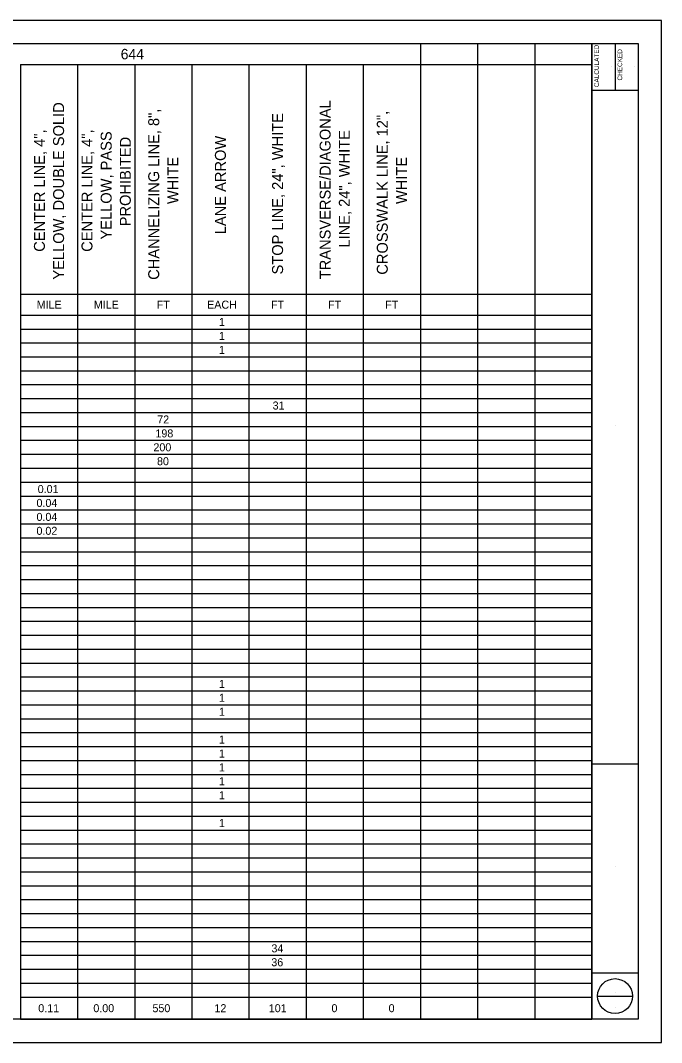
# Model space of a CAD drawing. Extents: x 10.3 to 44.3, y 3.4 to 25.4.
# Drawn here: x 30.51 to 44.31, y 3.4 to 25.4 of the extents above; entities that cross this region are included whole.
import ezdxf

# ---------------------------------------------------------------- set-up
doc = ezdxf.new("R2010")
doc.units = 0
for name, color, linetype in [('SH_Border', 7, 'Continuous'), ('SH_Cut_Line', 7, 'Continuous'), ('SH_Data', 7, 'Continuous'), ('SH_Text', 7, 'Continuous')]:
    doc.layers.add(name, color=color, linetype=linetype)

msp = doc.modelspace()

# ---------------------------------------------------------------- linework, layer by layer
at = {"layer": 'SH_Border'}
for p, q in [((42.806, 3.905), (42.806, 24.905)), ((43.306, 24.905), (43.306, 23.905)), ((42.806, 23.905), (43.806, 23.905)), ((42.806, 9.405), (43.806, 9.405)), ((42.806, 4.905), (43.806, 4.905))]:
    msp.add_line(p, q, dxfattribs=at)
msp.add_lwpolyline([(12.306, 24.905), (43.806, 24.905), (43.806, 3.905), (12.306, 3.905)], close=True, dxfattribs=at)
at = {"layer": 'SH_Cut_Line'}
msp.add_lwpolyline([(10.306, 3.405), (44.306, 3.405), (44.306, 25.405), (10.306, 25.405)], close=True, dxfattribs=at)
at = {"layer": 'SH_Data'}
for p, q in [((43.226, 24.408), (43.226, 24.408)), ((43.726, 24.408), (43.726, 24.408)), ((43.306, 16.696), (43.306, 16.696)), ((43.306, 7.196), (43.306, 7.196)), ((42.931, 4.405), (43.681, 4.405)), ((43.306, 4.49), (43.306, 4.49)), ((43.306, 4.15), (43.306, 4.15))]:
    msp.add_line(p, q, dxfattribs=at)
msp.add_circle((43.306, 4.405), 0.375, dxfattribs=at)
at = {"layer": 'SH_Text'}
for p, q in [((30.512, 24.905), (34.2, 24.905)), ((34.2, 24.905), (36.659, 24.905)), ((36.659, 24.905), (41.577, 24.905)), ((39.118, 24.905), (39.118, 12.173)), ((40.347, 24.905), (40.347, 12.173)), ((41.577, 24.905), (42.806, 24.905)), ((41.577, 24.905), (41.577, 12.173)), ((42.806, 24.905), (42.806, 12.173)), ((30.512, 24.455), (34.2, 24.455)), ((30.512, 24.455), (30.512, 12.173)), ((31.741, 24.455), (31.741, 12.173)), ((32.97, 24.455), (32.97, 12.173)), ((34.2, 24.455), (36.659, 24.455)), ((34.2, 24.455), (34.2, 12.173)), ((35.429, 24.455), (35.429, 12.173)), ((36.659, 24.455), (41.577, 24.455)), ((36.659, 24.455), (36.659, 12.173)), ((37.888, 24.455), (37.888, 12.173)), ((41.577, 24.455), (42.806, 24.455)), ((30.512, 19.512), (34.2, 19.512)), ((34.2, 19.512), (36.659, 19.512)), ((36.659, 19.512), (41.577, 19.512)), ((41.577, 19.512), (42.806, 19.512)), ((30.512, 19.063), (34.2, 19.063)), ((34.2, 19.063), (36.659, 19.063)), ((36.659, 19.063), (41.577, 19.063)), ((41.577, 19.063), (42.806, 19.063)), ((30.512, 18.763), (34.2, 18.763)), ((34.2, 18.763), (36.659, 18.763)), ((36.659, 18.763), (41.577, 18.763)), ((41.577, 18.763), (42.806, 18.763)), ((30.512, 18.464), (34.2, 18.464)), ((34.2, 18.464), (36.659, 18.464)), ((36.659, 18.464), (41.577, 18.464)), ((41.577, 18.464), (42.806, 18.464)), ((30.512, 18.164), (34.2, 18.164)), ((34.2, 18.164), (36.659, 18.164)), ((36.659, 18.164), (41.577, 18.164)), ((41.577, 18.164), (42.806, 18.164)), ((30.512, 17.865), (34.2, 17.865)), ((34.2, 17.865), (36.659, 17.865)), ((36.659, 17.865), (41.577, 17.865)), ((41.577, 17.865), (42.806, 17.865)), ((30.512, 17.565), (34.2, 17.565)), ((34.2, 17.565), (36.659, 17.565)), ((36.659, 17.565), (41.577, 17.565)), ((41.577, 17.565), (42.806, 17.565)), ((30.512, 17.265), (34.2, 17.265)), ((34.2, 17.265), (36.659, 17.265)), ((36.659, 17.265), (41.577, 17.265)), ((41.577, 17.265), (42.806, 17.265)), ((30.512, 16.966), (34.2, 16.966)), ((34.2, 16.966), (36.659, 16.966)), ((36.659, 16.966), (41.577, 16.966)), ((41.577, 16.966), (42.806, 16.966)), ((30.512, 16.666), (34.2, 16.666)), ((34.2, 16.666), (36.659, 16.666)), ((36.659, 16.666), (41.577, 16.666)), ((41.577, 16.666), (42.806, 16.666)), ((30.512, 16.367), (34.2, 16.367)), ((34.2, 16.367), (36.659, 16.367)), ((36.659, 16.367), (41.577, 16.367)), ((41.577, 16.367), (42.806, 16.367)), ((30.512, 16.067), (34.2, 16.067)), ((34.2, 16.067), (36.659, 16.067)), ((36.659, 16.067), (41.577, 16.067)), ((41.577, 16.067), (42.806, 16.067)), ((30.512, 15.768), (34.2, 15.768)), ((34.2, 15.768), (36.659, 15.768)), ((36.659, 15.768), (41.577, 15.768)), ((41.577, 15.768), (42.806, 15.768)), ((30.512, 15.468), (34.2, 15.468)), ((34.2, 15.468), (36.659, 15.468)), ((36.659, 15.468), (41.577, 15.468)), ((41.577, 15.468), (42.806, 15.468)), ((30.512, 15.168), (34.2, 15.168)), ((34.2, 15.168), (36.659, 15.168)), ((36.659, 15.168), (41.577, 15.168)), ((41.577, 15.168), (42.806, 15.168)), ((30.512, 14.869), (34.2, 14.869)), ((34.2, 14.869), (36.659, 14.869)), ((36.659, 14.869), (41.577, 14.869)), ((41.577, 14.869), (42.806, 14.869)), ((30.512, 14.569), (34.2, 14.569)), ((34.2, 14.569), (36.659, 14.569)), ((36.659, 14.569), (41.577, 14.569)), ((41.577, 14.569), (42.806, 14.569)), ((30.512, 14.27), (34.2, 14.27)), ((34.2, 14.27), (36.659, 14.27)), ((36.659, 14.27), (41.577, 14.27)), ((41.577, 14.27), (42.806, 14.27)), ((30.512, 13.97), (34.2, 13.97)), ((34.2, 13.97), (36.659, 13.97)), ((36.659, 13.97), (41.577, 13.97)), ((41.577, 13.97), (42.806, 13.97)), ((30.512, 13.671), (34.2, 13.671)), ((34.2, 13.671), (36.659, 13.671)), ((36.659, 13.671), (41.577, 13.671)), ((41.577, 13.671), (42.806, 13.671)), ((30.512, 13.371), (34.2, 13.371)), ((34.2, 13.371), (36.659, 13.371)), ((36.659, 13.371), (41.577, 13.371)), ((41.577, 13.371), (42.806, 13.371)), ((30.512, 13.071), (34.2, 13.071)), ((34.2, 13.071), (36.659, 13.071)), ((36.659, 13.071), (41.577, 13.071)), ((41.577, 13.071), (42.806, 13.071)), ((30.512, 12.772), (34.2, 12.772)), ((34.2, 12.772), (36.659, 12.772)), ((36.659, 12.772), (41.577, 12.772)), ((41.577, 12.772), (42.806, 12.772)), ((30.512, 12.472), (34.2, 12.472)), ((34.2, 12.472), (36.659, 12.472)), ((36.659, 12.472), (41.577, 12.472)), ((41.577, 12.472), (42.806, 12.472)), ((30.512, 12.173), (34.2, 12.173)), ((30.512, 12.173), (30.512, 3.905)), ((31.741, 12.173), (31.741, 3.905)), ((32.97, 12.173), (32.97, 3.905)), ((34.2, 12.173), (36.659, 12.173)), ((34.2, 12.173), (34.2, 3.905)), ((35.429, 12.173), (35.429, 3.905)), ((36.659, 12.173), (41.577, 12.173)), ((36.659, 12.173), (36.659, 3.905)), ((37.888, 12.173), (37.888, 3.905)), ((39.118, 12.173), (39.118, 3.905)), ((40.347, 12.173), (40.347, 3.905)), ((41.577, 12.173), (42.806, 12.173)), ((41.577, 12.173), (41.577, 3.905)), ((42.806, 12.173), (42.806, 3.905)), ((30.512, 11.873), (34.2, 11.873)), ((34.2, 11.873), (36.659, 11.873)), ((36.659, 11.873), (41.577, 11.873)), ((41.577, 11.873), (42.806, 11.873)), ((30.512, 11.574), (34.2, 11.574)), ((34.2, 11.574), (36.659, 11.574)), ((36.659, 11.574), (41.577, 11.574)), ((41.577, 11.574), (42.806, 11.574)), ((30.512, 11.274), (34.2, 11.274)), ((34.2, 11.274), (36.659, 11.274)), ((36.659, 11.274), (41.577, 11.274)), ((41.577, 11.274), (42.806, 11.274)), ((30.512, 10.974), (34.2, 10.974)), ((34.2, 10.974), (36.659, 10.974)), ((36.659, 10.974), (41.577, 10.974)), ((41.577, 10.974), (42.806, 10.974)), ((30.512, 10.675), (34.2, 10.675)), ((34.2, 10.675), (36.659, 10.675)), ((36.659, 10.675), (41.577, 10.675)), ((41.577, 10.675), (42.806, 10.675)), ((30.512, 10.375), (34.2, 10.375)), ((34.2, 10.375), (36.659, 10.375)), ((36.659, 10.375), (41.577, 10.375)), ((41.577, 10.375), (42.806, 10.375)), ((30.512, 10.076), (34.2, 10.076)), ((34.2, 10.076), (36.659, 10.076)), ((36.659, 10.076), (41.577, 10.076)), ((41.577, 10.076), (42.806, 10.076)), ((30.512, 9.776), (34.2, 9.776)), ((34.2, 9.776), (36.659, 9.776)), ((36.659, 9.776), (41.577, 9.776)), ((41.577, 9.776), (42.806, 9.776)), ((30.512, 9.477), (34.2, 9.477)), ((34.2, 9.477), (36.659, 9.477)), ((36.659, 9.477), (41.577, 9.477)), ((41.577, 9.477), (42.806, 9.477)), ((30.512, 9.177), (34.2, 9.177)), ((34.2, 9.177), (36.659, 9.177)), ((36.659, 9.177), (41.577, 9.177)), ((41.577, 9.177), (42.806, 9.177)), ((30.512, 8.877), (34.2, 8.877)), ((34.2, 8.877), (36.659, 8.877)), ((36.659, 8.877), (41.577, 8.877)), ((41.577, 8.877), (42.806, 8.877)), ((30.512, 8.578), (34.2, 8.578)), ((34.2, 8.578), (36.659, 8.578)), ((36.659, 8.578), (41.577, 8.578)), ((41.577, 8.578), (42.806, 8.578)), ((30.512, 8.278), (34.2, 8.278)), ((34.2, 8.278), (36.659, 8.278)), ((36.659, 8.278), (41.577, 8.278)), ((41.577, 8.278), (42.806, 8.278)), ((30.512, 7.979), (34.2, 7.979)), ((34.2, 7.979), (36.659, 7.979)), ((36.659, 7.979), (41.577, 7.979)), ((41.577, 7.979), (42.806, 7.979)), ((30.512, 7.679), (34.2, 7.679)), ((34.2, 7.679), (36.659, 7.679)), ((36.659, 7.679), (41.577, 7.679)), ((41.577, 7.679), (42.806, 7.679)), ((30.512, 7.38), (34.2, 7.38)), ((34.2, 7.38), (36.659, 7.38)), ((36.659, 7.38), (41.577, 7.38)), ((41.577, 7.38), (42.806, 7.38)), ((30.512, 7.08), (34.2, 7.08)), ((34.2, 7.08), (36.659, 7.08)), ((36.659, 7.08), (41.577, 7.08)), ((41.577, 7.08), (42.806, 7.08)), ((30.512, 6.78), (34.2, 6.78)), ((34.2, 6.78), (36.659, 6.78)), ((36.659, 6.78), (41.577, 6.78)), ((41.577, 6.78), (42.806, 6.78)), ((30.512, 6.481), (34.2, 6.481)), ((34.2, 6.481), (36.659, 6.481)), ((36.659, 6.481), (41.577, 6.481)), ((41.577, 6.481), (42.806, 6.481)), ((30.512, 6.181), (34.2, 6.181)), ((34.2, 6.181), (36.659, 6.181)), ((36.659, 6.181), (41.577, 6.181)), ((41.577, 6.181), (42.806, 6.181)), ((30.512, 5.882), (34.2, 5.882)), ((34.2, 5.882), (36.659, 5.882)), ((36.659, 5.882), (41.577, 5.882)), ((41.577, 5.882), (42.806, 5.882)), ((30.512, 5.582), (34.2, 5.582)), ((34.2, 5.582), (36.659, 5.582)), ((36.659, 5.582), (41.577, 5.582)), ((41.577, 5.582), (42.806, 5.582)), ((30.512, 5.283), (34.2, 5.283)), ((34.2, 5.283), (36.659, 5.283)), ((36.659, 5.283), (41.577, 5.283)), ((41.577, 5.283), (42.806, 5.283)), ((30.512, 4.983), (34.2, 4.983)), ((34.2, 4.983), (36.659, 4.983)), ((36.659, 4.983), (41.577, 4.983)), ((41.577, 4.983), (42.806, 4.983)), ((30.512, 4.683), (34.2, 4.683)), ((34.2, 4.683), (36.659, 4.683)), ((36.659, 4.683), (41.577, 4.683)), ((41.577, 4.683), (42.806, 4.683)), ((30.512, 4.384), (34.2, 4.384)), ((34.2, 4.384), (36.659, 4.384)), ((36.659, 4.384), (41.577, 4.384)), ((41.577, 4.384), (42.806, 4.384)), ((30.512, 3.905), (34.2, 3.905)), ((34.2, 3.905), (36.659, 3.905)), ((36.659, 3.905), (41.577, 3.905)), ((41.577, 3.905), (42.806, 3.905))]:
    msp.add_line(p, q, dxfattribs=at)

# ---------------------------------------------------------------- texts
at = {"layer": 'SH_Data'}
for s, p in [('CALCULATED', (42.959, 23.969)), ('CHECKED', (43.459, 24.112))]:
    msp.add_text(s, height=0.1, rotation=90, dxfattribs=at).set_placement(p)
at = {"layer": 'SH_Text'}
for s, height, p in [('644', 0.2239, (32.669, 24.568)), ('MILE', 0.1723, (30.861, 19.201)), ('MILE', 0.1723, (32.09, 19.201)), ('FT', 0.1723, (33.443, 19.201)), ('EACH', 0.1723, (34.528, 19.201)), ('FT', 0.1723, (35.902, 19.201)), ('FT', 0.1723, (37.131, 19.201)), ('FT', 0.1723, (38.36, 19.201)), ('1', 0.172, (34.781, 18.827)), ('1', 0.172, (34.781, 18.527)), ('1', 0.172, (34.781, 18.228)), ('31', 0.1723, (35.938, 17.03)), ('72', 0.1723, (33.455, 16.73)), ('198', 0.1723, (33.416, 16.43)), ('200', 0.1723, (33.373, 16.131)), ('80', 0.1723, (33.45, 15.831)), ('0.01', 0.1723, (30.883, 15.232)), ('0.04', 0.1723, (30.857, 14.933)), ('0.04', 0.1723, (30.857, 14.633)), ('0.02', 0.1723, (30.856, 14.333)), ('1', 0.172, (34.781, 11.038)), ('1', 0.172, (34.781, 10.739)), ('1', 0.172, (34.781, 10.439)), ('1', 0.172, (34.781, 9.84)), ('1', 0.172, (34.781, 9.54)), ('1', 0.172, (34.781, 9.241)), ('1', 0.172, (34.781, 8.941)), ('1', 0.172, (34.781, 8.642)), ('1', 0.172, (34.781, 8.042)), ('34', 0.1723, (35.912, 5.346)), ('36', 0.1723, (35.909, 5.047)), ('0.11', 0.1723, (30.895, 4.058)), ('0.00', 0.1723, (32.08, 4.058)), ('550', 0.1723, (33.352, 4.058)), ('12', 0.1723, (34.686, 4.058)), ('101', 0.1723, (35.855, 4.058)), ('0', 0.172, (37.204, 4.058)), ('0', 0.172, (38.433, 4.058))]:
    msp.add_text(s, height=height, dxfattribs=at).set_placement(p)
for s, height, p in [('YELLOW, DOUBLE SOLID', 0.23565, (31.45, 19.826)), ('TRANSVERSE/DIAGONAL', 0.23565, (37.185, 19.834)), ('CHANNELIZING LINE, 8",', 0.23565, (33.497, 19.822)), ('STOP LINE, 24", WHITE', 0.23565, (36.162, 19.937)), ('CROSSWALK LINE, 12",', 0.23565, (38.415, 19.932)), ('CENTER LINE, 4",', 0.23565, (31.038, 20.425)), ('CENTER LINE, 4",', 0.23565, (32.061, 20.425)), ('YELLOW, PASS', 0.23565, (32.474, 20.689)), ('PROHIBITED', 0.2356, (32.886, 20.974)), ('LANE ARROW', 0.2356, (34.932, 20.804)), ('LINE, 24", WHITE', 0.23565, (37.598, 20.516)), ('WHITE', 0.2356, (33.909, 21.453)), ('WHITE', 0.2356, (38.827, 21.453))]:
    msp.add_text(s, height=height, rotation=90, dxfattribs=at).set_placement(p)

doc.saveas('drawing.dxf')
